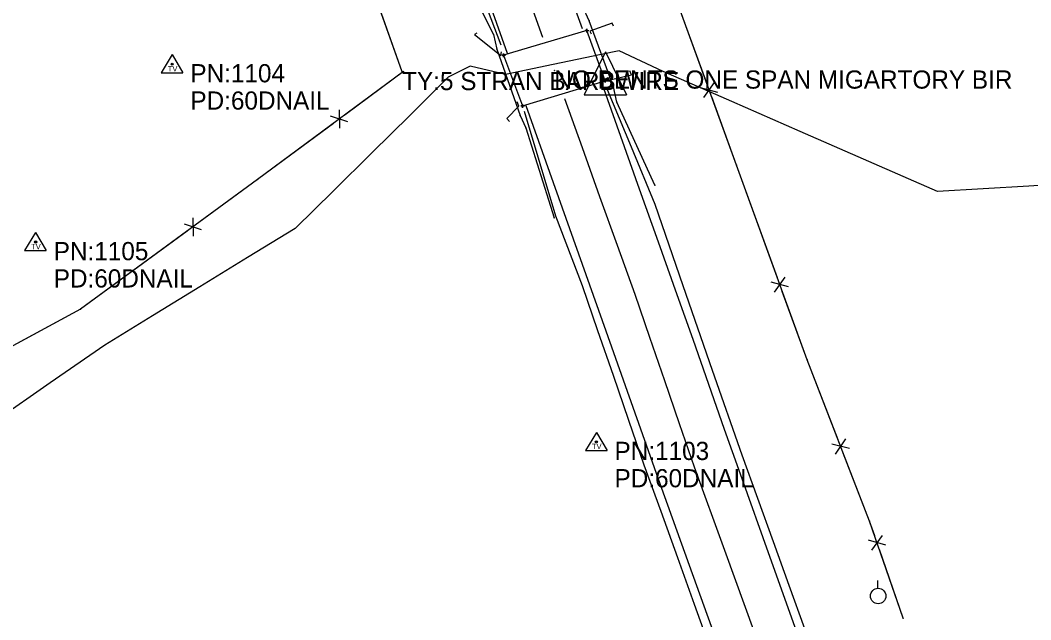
# Model space of a CAD drawing. Extents: x 1050807 to 1053552, y 395828 to 398415.
# Drawn here: x 1052358.5 to 1052636.4, y 396468 to 396632.8 of the extents above; entities that cross this region are included whole.
import ezdxf

# ---------------------------------------------------------------- set-up
doc = ezdxf.new("R2010")
doc.units = 0
for name, color, linetype in [('S_BRIDGE', 7, 'Continuous'), ('S_CAL_CORNER', 7, 'Continuous'), ('S_DITCHLINE', 7, 'Continuous'), ('S_EDGE_CONCRETE', 7, 'Continuous'), ('S_EDGE_PAVEMENT', 7, 'Continuous'), ('S_FENCE', 7, 'Continuous'), ('S_FENCE_ANNOT', 7, 'Continuous'), ('S_GUARDRAIL', 7, 'Continuous'), ('S_MSC_PT_SYM', 7, 'Continuous'), ('S_PAVEMENT_CROWN', 7, 'Continuous'), ('S_RDW_PT_SYM', 7, 'Continuous'), ('S_SECONDARY_CTL', 7, 'Continuous'), ('S_SECONDARY_CTL_ANNOT', 7, 'Continuous'), ('S_SHOULDER', 7, 'Continuous'), ('S_STR_PT_SYM', 7, 'Continuous'), ('S_SURVEY_TEXT_ANNOT', 7, 'Continuous'), ('S_UTILITY_POLE', 7, 'Continuous')]:
    doc.layers.add(name, color=color, linetype=linetype)

msp = doc.modelspace()

# ---------------------------------------------------------------- linework, layer by layer
at = {"layer": 'S_BRIDGE'}
for p, q in [((1052514.38, 396629.99), (1052491.48, 396623.21)), ((1052519.37, 396616.2), (1052514.38, 396629.99)), ((1052491.48, 396623.21), (1052496.68, 396609.27)), ((1052496.68, 396609.27), (1052519.37, 396616.2))]:
    msp.add_line(p, q, dxfattribs=at)
at = {"layer": 'S_CAL_CORNER'}
for p, q in [((1052519.46, 396624.18), (1052513.58, 396612.36)), ((1052519.46, 396624.18), (1052525.27, 396612.36)), ((1052513.58, 396612.36), (1052525.27, 396612.36))]:
    msp.add_line(p, q, dxfattribs=at)
at = {"layer": 'S_DITCHLINE'}
msp.add_lwpolyline([(1052648.44, 396588.03), (1052635.88, 396587.26), (1052623.33, 396586.5), (1052610.78, 396585.73), (1052591.91, 396593.99), (1052573.05, 396602.25), (1052554.19, 396610.51), (1052535.33, 396618.77), (1052523.26, 396624.46), (1052518.29, 396623.46), (1052505.12, 396620.71), (1052491.95, 396617.96), (1052482.23, 396620.23), (1052476.27, 396617.15), (1052465.74, 396606.75), (1052455.2, 396596.36), (1052444.67, 396585.97), (1052434.13, 396575.58), (1052421.05, 396567.57), (1052407.97, 396559.56), (1052394.89, 396551.55), (1052381.8, 396543.54), (1052366.79, 396533.11), (1052351.77, 396522.67)], dxfattribs=at)
at = {"layer": 'S_EDGE_CONCRETE'}
for points in [[(1052521.67, 396631.17), (1052521.32, 396632.07), (1052515.22, 396629.83), (1052515.53, 396629.11)], [(1052484.15, 396629.32), (1052483.47, 396628.95), (1052490.69, 396623.12), (1052490.89, 396624.12)], [(1052519.95, 396617.15), (1052520.3, 396616.35), (1052526.6, 396617.81), (1052526.16, 396618.89)], [(1052493.12, 396605), (1052492.32, 396605.85), (1052495.63, 396609.25), (1052495.22, 396610.44)]]:
    msp.add_lwpolyline(points, dxfattribs=at)
at = {"layer": 'S_EDGE_PAVEMENT'}
for points in [[(1052513.12, 396630.45), (1052508.63, 396642.96), (1052504.15, 396655.48), (1052499.67, 396667.99), (1052495.19, 396680.5), (1052490.88, 396692.59), (1052486.56, 396704.68), (1052482.25, 396716.78), (1052477.94, 396728.87), (1052472.12, 396745.25), (1052466.29, 396761.63)], [(1052492.52, 396623.71), (1052488.11, 396636.03), (1052483.7, 396648.36), (1052479.29, 396660.69), (1052474.88, 396673.01), (1052466.54, 396696.37), (1052458.19, 396719.73), (1052452.07, 396736.99), (1052445.94, 396754.24)], [(1052572.96, 396462.27), (1052564.78, 396485.14), (1052556.6, 396508.02), (1052552.25, 396520.35), (1052547.91, 396532.69), (1052543.56, 396545.03), (1052539.22, 396557.37), (1052534.05, 396571.87), (1052528.88, 396586.38), (1052523.71, 396600.88), (1052518.54, 396615.39)], [(1052550.61, 396460.54), (1052542.56, 396482.95), (1052534.52, 396505.36), (1052527.08, 396526.36), (1052519.65, 396547.35), (1052514.14, 396562.84), (1052508.64, 396578.34), (1052503.13, 396593.83), (1052497.63, 396609.32)]]:
    msp.add_lwpolyline(points, dxfattribs=at)
at = {"layer": 'S_FENCE'}
for p, q in [((1052541.18, 396632.28), (1052521.09, 396688.84)), ((1052463.57, 396618.62), (1052445.33, 396670.2)), ((1052555.55, 396593.01), (1052541.18, 396632.28)), ((1052463.95, 396618.78), (1052423.81, 396589.01)), ((1052546.57, 396611.6), (1052549.43, 396615.7)), ((1052546.57, 396611.6), (1052549.43, 396615.7)), ((1052550.42, 396613.01), (1052545.59, 396614.29)), ((1052550.42, 396613.01), (1052545.59, 396614.29)), ((1052446.21, 396608.17), (1052446.35, 396603.18)), ((1052446.21, 396608.17), (1052446.35, 396603.18)), ((1052448.65, 396604.88), (1052443.91, 396606.47)), ((1052448.65, 396604.88), (1052443.91, 396606.47)), ((1052574.9, 396539.47), (1052555.55, 396593.01)), ((1052423.81, 396589.01), (1052375.15, 396553.36)), ((1052408.43, 396575.2), (1052403.69, 396576.81)), ((1052408.43, 396575.2), (1052403.69, 396576.81)), ((1052406.01, 396578.5), (1052406.11, 396573.5)), ((1052406.01, 396578.5), (1052406.11, 396573.5)), ((1052569.84, 396559.5), (1052565.02, 396560.8)), ((1052569.84, 396559.5), (1052565.02, 396560.8)), ((1052565.99, 396558.11), (1052568.87, 396562.2)), ((1052565.99, 396558.11), (1052568.87, 396562.2)), ((1052375.15, 396553.36), (1052312.57, 396519.69)), ((1052592.12, 396495.16), (1052574.9, 396539.47)), ((1052586.58, 396515.07), (1052581.73, 396516.26)), ((1052586.58, 396515.07), (1052581.73, 396516.26)), ((1052582.76, 396513.58), (1052585.54, 396517.74)), ((1052582.76, 396513.58), (1052585.54, 396517.74)), ((1052601.32, 396468.43), (1052592.12, 396495.16)), ((1052592.71, 396487.16), (1052595.65, 396491.2)), ((1052592.71, 396487.16), (1052595.65, 396491.2)), ((1052596.58, 396488.49), (1052591.77, 396489.87)), ((1052596.58, 396488.49), (1052591.77, 396489.87))]:
    msp.add_line(p, q, dxfattribs=at)
for points in [[(1052541.18, 396632.28), (1052534.49, 396651.12)], [(1052541.18, 396632.28), (1052534.49, 396651.12)], [(1052463.57, 396618.62), (1052456.9, 396637.48)], [(1052463.57, 396618.62), (1052456.9, 396637.48)], [(1052547.31, 396615.52), (1052541.18, 396632.28)], [(1052547.31, 396615.52), (1052541.18, 396632.28)], [(1052463.95, 396618.78), (1052447.89, 396606.87)], [(1052463.95, 396618.78), (1052447.89, 396606.87)], [(1052555.55, 396593.01), (1052548.69, 396611.77)], [(1052555.55, 396593.01), (1052548.69, 396611.77)], [(1052444.67, 396604.48), (1052423.81, 396589.01)], [(1052444.67, 396604.48), (1052423.81, 396589.01)], [(1052566.75, 396562.03), (1052555.55, 396593.01)], [(1052566.75, 396562.03), (1052555.55, 396593.01)], [(1052423.81, 396589.01), (1052407.67, 396577.19)], [(1052423.81, 396589.01), (1052407.67, 396577.19)], [(1052404.45, 396574.82), (1052375.15, 396553.36)], [(1052404.45, 396574.82), (1052375.15, 396553.36)], [(1052574.9, 396539.47), (1052568.11, 396558.27)], [(1052574.9, 396539.47), (1052568.11, 396558.27)], [(1052375.15, 396553.36), (1052357.54, 396543.88)], [(1052375.15, 396553.36), (1052357.54, 396543.88)], [(1052583.43, 396517.52), (1052574.9, 396539.47)], [(1052583.43, 396517.52), (1052574.9, 396539.47)], [(1052592.12, 396495.16), (1052584.88, 396513.8)], [(1052592.12, 396495.16), (1052584.88, 396513.8)], [(1052593.53, 396491.07), (1052592.12, 396495.16)], [(1052593.53, 396491.07), (1052592.12, 396495.16)], [(1052601.32, 396468.43), (1052594.83, 396487.29)], [(1052601.32, 396468.43), (1052594.83, 396487.29)]]:
    msp.add_lwpolyline(points, dxfattribs=at)
at = {"layer": 'S_GUARDRAIL'}
for p, q in [((1052477.08, 396652.19), (1052488.66, 396628.95)), ((1052514.96, 396632.69), (1052513.23, 396636.52)), ((1052521.7, 396614.49), (1052514.96, 396632.69)), ((1052488.66, 396628.95), (1052489.57, 396624.93)), ((1052489.57, 396624.93), (1052495.98, 396606.61)), ((1052522.63, 396610.33), (1052521.7, 396614.49)), ((1052533.09, 396587.5), (1052522.63, 396610.33)), ((1052495.98, 396606.61), (1052497.61, 396603.26)), ((1052497.61, 396603.26), (1052505.37, 396578.52))]:
    msp.add_line(p, q, dxfattribs=at)
at = {"layer": 'S_MSC_PT_SYM'}
for points in [[(1052541.18, 396632.28), (1052541.18, 396632.33), (1052541.18, 396632.28), (1052541.13, 396632.28), (1052541.18, 396632.28), (1052541.18, 396632.23), (1052541.18, 396632.28), (1052541.23, 396632.28)], [(1052463.57, 396618.62), (1052463.57, 396618.67), (1052463.57, 396618.62), (1052463.52, 396618.62), (1052463.57, 396618.62), (1052463.57, 396618.57), (1052463.57, 396618.62), (1052463.62, 396618.62)], [(1052463.95, 396618.78), (1052463.95, 396618.83), (1052463.95, 396618.78), (1052463.9, 396618.78), (1052463.95, 396618.78), (1052463.95, 396618.73), (1052463.95, 396618.78), (1052464, 396618.78)], [(1052505.44, 396619.04), (1052505.44, 396619.09), (1052505.44, 396619.04), (1052505.39, 396619.04), (1052505.44, 396619.04), (1052505.44, 396618.99), (1052505.44, 396619.04), (1052505.49, 396619.04)], [(1052555.55, 396593.01), (1052555.55, 396593.06), (1052555.55, 396593.01), (1052555.5, 396593.01), (1052555.55, 396593.01), (1052555.55, 396592.96), (1052555.55, 396593.01), (1052555.6, 396593.01)], [(1052423.81, 396589.01), (1052423.81, 396589.06), (1052423.81, 396589.01), (1052423.76, 396589.01), (1052423.81, 396589.01), (1052423.81, 396588.96), (1052423.81, 396589.01), (1052423.86, 396589.01)], [(1052375.15, 396553.36), (1052375.15, 396553.41), (1052375.15, 396553.36), (1052375.1, 396553.36), (1052375.15, 396553.36), (1052375.15, 396553.31), (1052375.15, 396553.36), (1052375.2, 396553.36)], [(1052574.9, 396539.47), (1052574.9, 396539.52), (1052574.9, 396539.47), (1052574.85, 396539.47), (1052574.9, 396539.47), (1052574.9, 396539.42), (1052574.9, 396539.47), (1052574.95, 396539.47)], [(1052592.12, 396495.16), (1052592.12, 396495.21), (1052592.12, 396495.16), (1052592.07, 396495.16), (1052592.12, 396495.16), (1052592.12, 396495.11), (1052592.12, 396495.16), (1052592.17, 396495.16)], [(1052601.32, 396468.43), (1052601.32, 396468.48), (1052601.32, 396468.43), (1052601.27, 396468.43), (1052601.32, 396468.43), (1052601.32, 396468.38), (1052601.32, 396468.43), (1052601.37, 396468.43)]]:
    msp.add_lwpolyline(points, dxfattribs=at)
at = {"layer": 'S_PAVEMENT_CROWN'}
for points in [[(1052502.26, 396628.13), (1052497.86, 396640.46), (1052493.46, 396652.79), (1052489.06, 396665.12), (1052484.66, 396677.44), (1052480.34, 396689.57), (1052476.02, 396701.7), (1052471.71, 396713.83), (1052467.39, 396725.96), (1052461.95, 396741.7), (1052456.52, 396757.45)], [(1052560.66, 396464.06), (1052552.31, 396487.03), (1052543.96, 396509.99), (1052539.88, 396521.85), (1052535.8, 396533.71), (1052531.72, 396545.57), (1052527.64, 396557.43), (1052522.8, 396570.88), (1052517.97, 396584.32), (1052513.13, 396597.77), (1052508.29, 396611.21)]]:
    msp.add_lwpolyline(points, dxfattribs=at)
at = {"layer": 'S_RDW_PT_SYM'}
for points in [[(1052514.96, 396632.69), (1052514.96, 396632.74), (1052514.96, 396632.69), (1052514.91, 396632.69), (1052514.96, 396632.69), (1052514.96, 396632.64), (1052514.96, 396632.69), (1052515.01, 396632.69)], [(1052488.66, 396628.95), (1052488.66, 396629), (1052488.66, 396628.95), (1052488.61, 396628.95), (1052488.66, 396628.95), (1052488.66, 396628.9), (1052488.66, 396628.95), (1052488.71, 396628.95)], [(1052489.57, 396624.93), (1052489.57, 396624.98), (1052489.57, 396624.93), (1052489.52, 396624.93), (1052489.57, 396624.93), (1052489.57, 396624.88), (1052489.57, 396624.93), (1052489.62, 396624.93)], [(1052521.7, 396614.49), (1052521.7, 396614.54), (1052521.7, 396614.49), (1052521.65, 396614.49), (1052521.7, 396614.49), (1052521.7, 396614.44), (1052521.7, 396614.49), (1052521.75, 396614.49)], [(1052522.63, 396610.33), (1052522.63, 396610.38), (1052522.63, 396610.33), (1052522.58, 396610.33), (1052522.63, 396610.33), (1052522.63, 396610.28), (1052522.63, 396610.33), (1052522.68, 396610.33)], [(1052495.98, 396606.61), (1052495.98, 396606.66), (1052495.98, 396606.61), (1052495.93, 396606.61), (1052495.98, 396606.61), (1052495.98, 396606.56), (1052495.98, 396606.61), (1052496.03, 396606.61)], [(1052497.61, 396603.26), (1052497.61, 396603.31), (1052497.61, 396603.26), (1052497.56, 396603.26), (1052497.61, 396603.26), (1052497.61, 396603.21), (1052497.61, 396603.26), (1052497.66, 396603.26)], [(1052533.09, 396587.5), (1052533.09, 396587.55), (1052533.09, 396587.5), (1052533.04, 396587.5), (1052533.09, 396587.5), (1052533.09, 396587.45), (1052533.09, 396587.5), (1052533.14, 396587.5)], [(1052505.37, 396578.52), (1052505.37, 396578.57), (1052505.37, 396578.52), (1052505.32, 396578.52), (1052505.37, 396578.52), (1052505.37, 396578.47), (1052505.37, 396578.52), (1052505.42, 396578.52)]]:
    msp.add_lwpolyline(points, dxfattribs=at)
at = {"layer": 'S_SECONDARY_CTL'}
for p, q in [((1052400.34, 396623.38), (1052397.33, 396618.42)), ((1052400.34, 396623.38), (1052403.28, 396618.42)), ((1052397.33, 396618.42), (1052403.28, 396618.42)), ((1052362.77, 396574.47), (1052359.76, 396569.51)), ((1052362.77, 396574.47), (1052365.71, 396569.51)), ((1052359.76, 396569.51), (1052365.71, 396569.51)), ((1052516.97, 396519.54), (1052513.96, 396514.59)), ((1052516.97, 396519.54), (1052519.92, 396514.59)), ((1052513.96, 396514.59), (1052519.92, 396514.59))]:
    msp.add_line(p, q, dxfattribs=at)
for centre, radius in [((1052400.34, 396620.77), 0.311), ((1052400.34, 396620.77), 0.183), ((1052400.34, 396620.77), 0.103), ((1052362.77, 396571.86), 0.311), ((1052362.77, 396571.86), 0.183), ((1052362.77, 396571.86), 0.103), ((1052516.97, 396516.93), 0.311), ((1052516.97, 396516.93), 0.183), ((1052516.97, 396516.93), 0.103)]:
    msp.add_circle(centre, radius, dxfattribs=at)
at = {"layer": 'S_SHOULDER'}
for points in [[(1052490.84, 396625.96), (1052484.29, 396643.25), (1052477.73, 396660.54), (1052470.26, 396681.35), (1052462.79, 396702.15), (1052457.16, 396718.73), (1052451.54, 396735.31), (1052445.27, 396753.86)], [(1052574.27, 396465.52), (1052569.96, 396477.46), (1052565.66, 396489.4), (1052561.35, 396501.34), (1052557.04, 396513.28), (1052548.93, 396536.57), (1052540.82, 396559.85), (1052533.17, 396582.21), (1052526.62, 396597.98), (1052520.06, 396613.74)], [(1052548.56, 396459.48), (1052543.95, 396472.24), (1052539.35, 396484.99), (1052534.75, 396497.74), (1052530.14, 396510.49), (1052525.9, 396522.82), (1052521.65, 396535.15), (1052517.4, 396547.48), (1052513.15, 396559.81), (1052505.87, 396579), (1052501.53, 396593.37), (1052497.18, 396607.74)]]:
    msp.add_lwpolyline(points, dxfattribs=at)
at = {"layer": 'S_STR_PT_SYM'}
for points in [[(1052514.38, 396629.99), (1052514.38, 396630.49), (1052514.38, 396629.99), (1052513.88, 396629.99), (1052514.38, 396629.99), (1052514.38, 396629.49), (1052514.38, 396629.99), (1052514.88, 396629.99)], [(1052491.48, 396623.21), (1052491.48, 396623.71), (1052491.48, 396623.21), (1052490.98, 396623.21), (1052491.48, 396623.21), (1052491.48, 396622.71), (1052491.48, 396623.21), (1052491.98, 396623.21)], [(1052519.37, 396616.2), (1052519.37, 396616.7), (1052519.37, 396616.2), (1052518.87, 396616.2), (1052519.37, 396616.2), (1052519.37, 396615.7), (1052519.37, 396616.2), (1052519.87, 396616.2)], [(1052496.68, 396609.27), (1052496.68, 396609.77), (1052496.68, 396609.27), (1052496.18, 396609.27), (1052496.68, 396609.27), (1052496.68, 396608.77), (1052496.68, 396609.27), (1052497.18, 396609.27)]]:
    msp.add_lwpolyline(points, dxfattribs=at)
at = {"layer": 'S_UTILITY_POLE'}
msp.add_line((1052594.34, 396476.68), (1052594.34, 396478.79), dxfattribs=at)
msp.add_circle((1052594.47, 396474.54), 2.13, dxfattribs=at)

# ---------------------------------------------------------------- texts
at = {"layer": 'S_FENCE_ANNOT'}
msp.add_text('TY:5 STRAN BARBWIRE', height=5, dxfattribs=at).set_placement((1052463.57, 396613.62))
at = {"layer": 'S_SECONDARY_CTL'}
for p in [(1052399.13, 396618.75), (1052361.56, 396569.85), (1052515.77, 396514.92)]:
    msp.add_text('TV', height=1.5, dxfattribs=at).set_placement(p)
at = {"layer": 'S_SECONDARY_CTL_ANNOT'}
for s, p in [('PN:1104', (1052405.34, 396615.77)), ('PD:60DNAIL', (1052405.34, 396608.27)), ('PN:1105', (1052367.77, 396566.86)), ('PD:60DNAIL', (1052367.77, 396559.36)), ('PN:1103', (1052521.97, 396511.93)), ('PD:60DNAIL', (1052521.97, 396504.43))]:
    msp.add_text(s, height=5, dxfattribs=at).set_placement(p)
at = {"layer": 'S_SURVEY_TEXT_ANNOT'}
msp.add_text('NO BENTS ONE SPAN MIGARTORY BIR', height=5, dxfattribs=at).set_placement((1052505.44, 396614.04))

doc.saveas('drawing.dxf')
